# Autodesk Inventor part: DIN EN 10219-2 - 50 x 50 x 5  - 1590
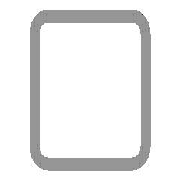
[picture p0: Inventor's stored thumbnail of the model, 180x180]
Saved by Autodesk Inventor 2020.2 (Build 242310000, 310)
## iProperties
_CCFamilyMember: 16
_CCFamilyDisplayName: DIN EN 10219-2 (Quadratisches Hohlprofil - Kaltgeformt) - Kaltgeformte, geschweißte Baustahl-Hohlprofile aus unlegiertem Feinkorn-Baustahl
_FrameMemberDoc: Frame Member File
_Version: 15.0.0
_GetPNFromCC: 1
IsCustomPart: 1
Created: 2019-01
Part Number: DIN EN 10219-2 - 50 x 50 x 5  - 1590
Material: Stahl, weich
Description: Kaltgeformte, geschweißte Baustahl-Hohlprofile aus unlegiertem Feinkorn-Baustahl
Document SubType Name: Modeling
Standard: DIN EN 10219-2
Designer: lutzd
Standard Revision: 2006-07
Standards Organization: DIN
Language: de-DE
Size Designation: 50 x 50 x 5
Categories: <MemberInstance><Categories><Category DisplayName="Profile" InternalName="089c4875-fa83-4c05-b084-43b9cc11f5ed" Mnemonic="GRDR"><CategoryParameter DisplayName="
Stock Number: 50 x 50 x 5
Mass: 10416.2 g
Surface Area: 5334.75 cm^2
Volume: 1326.9 cm^3
Density: 7.85 g/cm^3
Appearance: Semi-Polished(8)
G_W: 50,000 mm
G_H: 50,000 mm
G_L: 1590,000 mm
DocNumber: ADSK-014437
Folder: .
Mass: 10,416 kg
VLT_Material: Stahl, weich
Dimensions: 50x50x1590 mm
Title: Profil-Bauteil
Author: lutzd
Revision Number: -
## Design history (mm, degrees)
node "Startebene"
node "Endebene"
sketch "Skizze"
  geometry: L1 (-25, -15)-(-25, 15); L2 (-15, 25)-(15, 25); L3 (25, 15)-(25, -15); L4 (15, -25)-(-15, -25); L5 (-15, 20)-(15, 20); L6 (20, 15)-(20, -15); L7 (15, -20)-(-15, -20); L8 (-20, -15)-(-20, 15); L9 (0, 37.899)-(0, -37.899) reference; L10 (-37.899, 0)-(37.899, 0) reference; A1 r 10 centre (-15, -15) between (-25, -15) and (-15, -25); A2 r 10 centre (-15, 15) between (-15, 25) and (-25, 15); A3 r 10 centre (15, 15) between (25, 15) and (15, 25); A4 r 10 centre (15, -15) between (15, -25) and (25, -15); A5 r 5 centre (-15, 15) between (-15, 20) and (-20, 15); A6 r 5 centre (15, 15) between (20, 15) and (15, 20); A7 r 5 centre (15, -15) between (15, -20) and (20, -15); A8 r 5 centre (-15, -15) between (-20, -15) and (-15, -20)
  constraints: 16 end point, 16 point on circle, 8 centre point, 8 tangent, 4 parallel, 3 equal radius, 2 perpendicular, 7 other
  dimensions: "d7" = 10 radius of A1 (= G_IR); "d10" = 50 distance between parallel lines of L2 L4 (= G_H); "d11" = 50 distance between parallel lines of L1 L3 (= G_W); "d12" = 5 distance between parallel lines of L3 L6 (= G_T); "d15" = 25 distance between parallel lines of L2 L10 (= 0.5 x d10); "d16" = 25 distance between parallel lines of L9 L3 (= 0.5 x d11)
extrude "Körper" new body sketch "Skizze" stored distance "d3" = 1590 (= G_L); taper "d4" = 0 deg
node "Driven Length"
  sketch "Sketch3"
    geometry: L1 (0, 0)-(10, 0) reference
    constraints: 2 end point, 1 horizontal
  workplane "Work Plane3"
  sketch "Sketch4"
    geometry: L1 (-2, 0)-(12, 0) reference; L2 (-2, 1590)-(12, 1590) reference
    dimensions: "d18" = 1590 distance between parallel lines of L1 L2 (derived)
sketch "Skizze5"
  geometry: L1 (1590, 30)-(1590, 0) reference; L2 (1590, 15)-(605, 15); 4 further points
  constraints: 3 point on line, 2 end point, 1 coincident, 1 horizontal
  dimensions: "d19" = 35 distance of point (640, 15) point (605, 15); "d20" = 985 distance of L2.start L2.end; "d21" = 35 distance of point (1503, 15) point (1468, 15) (= d19); "d22" = 87 distance of L2.start point (1503, 15)
hole "Bohrung1" sketch "Skizze5" at (605, 15), (640, 15), (1468, 15), (1503, 15) diameter "d23" = 6.647; stored, may be unused: countersink angle "d27" = 90 deg, drill point angle "d29" = 118 deg; dims "d24" = 16, "d25" = 4, "d26" = 2, "d28" = 8
sketch "Skizze6"
  geometry: L1 (-30, 0)-(0, 0) reference; L2 (-15, 0)-(-15, 80); 2 further points
  constraints: 2 end point, 1 coincident, 1 midpoint, 1 vertical
  dimensions: "d30" = 80 distance of L2.start L2.end
hole "Bohrung2" sketch "Skizze6" at (-15, 80) diameter "d31" = 6.647; stored, may be unused: countersink angle "d35" = 90 deg, drill point angle "d37" = 118 deg; dims "d32" = 16, "d33" = 4, "d34" = 2, "d36" = 8
sketch "Skizze7"
  geometry: L1 (1590, -30)-(1590, 0) reference; L2 (1590, -15)-(1540, -15); 2 further points
  constraints: 2 end point, 1 coincident, 1 horizontal, 1 midpoint
  dimensions: "d38" = 50 distance of L2.start L2.end
hole "Bohrung3" sketch "Skizze7" at (1540, -15) diameter "d39" = 6.647; stored, may be unused: countersink angle "d43" = 90 deg, drill point angle "d45" = 118 deg; dims "d40" = 16, "d41" = 4, "d42" = 2, "d44" = 8
sketch "Skizze8"
  geometry: L1 (30, 1590)-(0, 1590) reference; L2 (15, 1590)-(15, 1509); 5 further points
  constraints: 2 end point, 1 coincident, 1 midpoint, 1 point on line, 1 vertical, 1 vertical alignment
  dimensions: "d46" = 62 distance of point (15, 1509) point (15, 1571); "d47" = 81 distance of L2.start L2.end; "d56" = 424 vertical distance of point (15, 1509) point (9, 1085); "d57" = 6 horizontal distance of point (9, 1085) L2.start; "d58" = 865 distance of point (9, 220) point (9, 1085)
hole "Bohrung4" sketch "Skizze8" at (15, 1571), (15, 1509), (9, 1085), (9, 220) diameter "d48" = 6.647; stored, may be unused: countersink angle "d52" = 90 deg, drill point angle "d54" = 118 deg; dims "d49" = 16, "d50" = 4, "d51" = 2, "d53" = 8
body "Solid1"
other parameters: "G_W" = 50 [user parameter; used in 1 equation term], "G_H" = 50 [user parameter; used in 1 equation term], "G_T" = 5 [user parameter; used in 1 equation term], "G_IR" = 10 [user parameter; used in 1 equation term], "G_L" = 1590 (= d18) [user parameter; used in 1 equation term], "G_OFFSET_START" = 0 [user parameter; used in 1 equation term], "G_OFFSET_END" = 0 [user parameter; used in 1 equation term], "d13" = 0 (computed from G_OFFSET_START), "d17" = 90 deg
